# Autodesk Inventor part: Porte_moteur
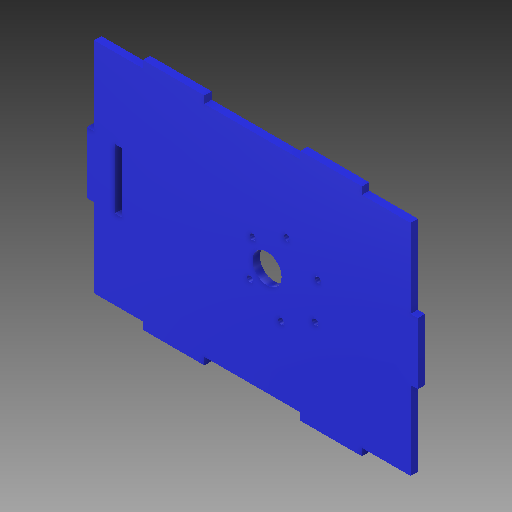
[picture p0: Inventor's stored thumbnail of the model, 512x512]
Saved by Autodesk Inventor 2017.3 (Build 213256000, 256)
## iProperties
Part Number: Porte_moteur
Material: Générique
Document SubType Name: Modeling
Designer: ficho
Density: 1 g/cm^3
Appearance: Bleu - Peinture murale - Brillant
Author: ficho
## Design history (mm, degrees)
sketch "Esquisse1"
  geometry: L1 (54.979, 13.833)-(54.979, -11.467); L2 (-81.021, -11.467)-(-81.021, 13.833); L3 (51.979, 13.833)-(54.979, 13.833); L4 (54.979, 13.833)-(54.979, -11.467); L5 (54.979, -11.467)-(51.979, -11.467); L6 (31.979, 49.183)-(6.679, 49.183); L7 (6.679, 49.183)-(6.679, 46.183); L8 (31.979, 46.183)-(31.979, 49.183); L9 (-32.721, 49.183)-(-58.021, 49.183); L10 (-58.021, 49.183)-(-58.021, 46.183); L11 (-32.721, 46.183)-(-32.721, 49.183); L12 (31.979, -43.817)-(31.979, -46.817); L13 (31.979, -46.817)-(6.679, -46.817); L14 (6.679, -46.817)-(6.679, -43.817); L15 (-58.021, -43.817)-(-58.021, -46.817); L16 (-58.021, -46.817)-(-32.721, -46.817); L17 (-32.721, -46.817)-(-32.721, -43.817); L18 (-78.021, 13.833)-(-81.021, 13.833); L19 (-81.021, 13.833)-(-81.021, -11.467); L20 (-81.021, -11.467)-(-78.021, -11.467); L21 (51.979, -43.817)-(51.979, -11.467); L22 (51.979, 13.833)-(51.979, 46.183); L23 (-58.021, 49.183)-(-32.721, 49.183); L24 (6.679, 49.183)-(31.979, 49.183); L25 (31.979, -46.817)-(6.679, -46.817); L26 (-32.721, -46.817)-(-58.021, -46.817); L27 (31.979, -43.817)-(51.979, -43.817); L28 (51.979, 46.183)-(31.979, 46.183); L29 (6.679, 46.183)-(-32.721, 46.183); L30 (-58.021, 46.183)-(-78.021, 46.183); L31 (-78.021, -43.817)-(-58.021, -43.817); L32 (-32.721, -43.817)-(6.679, -43.817); L33 (-78.021, 46.183)-(-78.021, 13.833); L34 (-78.021, -11.467)-(-78.021, -43.817); C1 r 6 at (-6.986, 0.448) reference; C2 r 1.229 at (-13.95, -6.757) reference; C3 r 1.229 at (12.827, -8.702) reference; C4 r 1.229 at (1.123, 15.459) reference; C5 r 1.229 at (13.95, 6.757) reference; C6 r 1.229 at (-1.123, -15.459) reference; C7 r 1.229 at (-12.827, 8.702) reference; 3 further points
  constraints: 68 end point, 24 parallel, 12 perpendicular, 6 horizontal, 1 point on line, 2 other
  dimensions: "d1" = 25.3 distance between parallel lines of L7 L8; "d2" = 25.3 distance between parallel lines of L10 L11 (= d1); "d3" = 25.3 distance between parallel lines of L15 L17 (= d4); "d4" = 25.3 distance between parallel lines of L14 L12 (= d5); "d5" = 25.3 distance between parallel lines of L5 L3 (= d1); "d6" = 25.3 distance between parallel lines of L20 L18 (= d3)
extrude "Extrusion1" new body sketch "Esquisse1" distance "d15" = 3; taper "d16" = 0 deg
sketch "Esquisse2"
  geometry: L1 (31.979, 49.183)-(6.679, 49.183) reference; L2 (6.679, 49.183)-(6.679, 46.183) reference; L3 (6.679, 46.183)-(-32.721, 46.183) reference; L4 (-32.721, 46.183)-(-32.721, 49.183) reference; L5 (-32.721, 49.183)-(-58.021, 49.183) reference; L6 (-58.021, 49.183)-(-58.021, 46.183) reference; L7 (-58.021, 46.183)-(-78.021, 46.183) reference; L8 (-78.021, 46.183)-(-78.021, 13.833) reference; L9 (-78.021, 13.833)-(-81.021, 13.833) reference; L10 (-81.021, 13.833)-(-81.021, -11.467) reference; L11 (-81.021, -11.467)-(-78.021, -11.467) reference; L12 (-78.021, -11.467)-(-78.021, -43.817) reference; L13 (-78.021, -43.817)-(-58.021, -43.817) reference; L14 (-58.021, -43.817)-(-58.021, -46.817) reference; L15 (-58.021, -46.817)-(-32.721, -46.817) reference; L16 (-32.721, -46.817)-(-32.721, -43.817) reference; L17 (-32.721, -43.817)-(6.679, -43.817) reference; L18 (6.679, -43.817)-(6.679, -46.817) reference; L19 (6.679, -46.817)-(31.979, -46.817) reference; L20 (31.979, -46.817)-(31.979, -43.817) reference; L21 (31.979, -43.817)-(51.979, -43.817) reference; L22 (51.979, -43.817)-(51.979, -11.467) reference; L23 (51.979, -11.467)-(54.979, -11.467) reference; L24 (54.979, -11.467)-(54.979, 13.833) reference; L25 (54.979, 13.833)-(51.979, 13.833) reference; L26 (51.979, 13.833)-(51.979, 46.183) reference; L27 (51.979, 46.183)-(31.979, 46.183) reference; L28 (31.979, 46.183)-(31.979, 49.183) reference; L29 (-66.521, 13.833)-(-66.521, -11.467) reference; L30 (-69.521, -11.467)-(-69.521, 13.833) reference; L31 (-66.521, -11.167)-(-69.521, -11.167); L32 (-69.521, -11.167)-(-69.521, 13.533); L33 (-69.521, 13.533)-(-66.521, 13.533); L34 (-66.521, 13.533)-(-66.521, -11.167); C1 r 6 at (-6.986, 0.448) reference; C2 r 1.229 at (-12.827, 8.702) reference; C3 r 1.229 at (-1.123, -15.459) reference; C4 r 1.229 at (13.95, 6.757) reference; C5 r 1.229 at (1.123, 15.459) reference; C6 r 1.229 at (12.827, -8.702) reference; C7 r 1.229 at (-13.95, -6.757) reference; 1 further point
  constraints: 8 end point, 2 parallel, 2 point on line, 1 horizontal, 1 perpendicular
  dimensions: "d17" = 0.3 distance from line of L31 L29.end; "d18" = 0.3 distance from line of L33 L29.start (= d17)
extrude "Extrusion2" cut sketch "Esquisse2" stored distance "d19" = 3; taper "d20" = 0 deg
node "Solide1"
node "Boucle projetée1"
node "Référence2"
node "Référence3"
other parameters: "d0" = 3, "d11" = 32.35, "d12" = 32.35 (derived), "d13" = 32.35, "d14" = 32.35 (derived)
